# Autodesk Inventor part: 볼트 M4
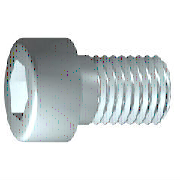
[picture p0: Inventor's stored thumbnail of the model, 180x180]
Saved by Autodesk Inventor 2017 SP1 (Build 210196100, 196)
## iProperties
IsCustomPart: 1
Created: 2012-02
Part Number: 볼트 M4
Material: 강철, 연강
Description: 6각머리 태핑 나사
Document SubType Name: Modeling
Standard: KS B 1003
Designer: mduedu
Standards Organization: KS
Language: ko-KR
Size Designation: M 4 x 10
Categories: <MemberInstance><Categories><Category DisplayName="조임쇠" InternalName="e4da775c-781d-43d5-af7c-5136215cf5a6" Mnemonic="FSTN"><Category DisplayName="볼트" InternalN
Density: 7.86 g/cm^3
Mass: 2.0371 g
Surface Area: 3.0572 cm^2
Volume: 0.259174 cm^3
Appearance: 강철
Author: mduedu
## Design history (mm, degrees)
sketch "스케치1"
  geometry: L1 (-1, 0)-(10, 0); L2 (10, 0)-(10, 2); L3 (10, 2)-(1.75, 2); L4 (1.75, 2)-(1.32, 2); L5 (1.32, 2)-(0, 2); L6 (0, 2)-(0, 3.5); L7 (0, 3.5)-(-4, 3.5); L8 (-4, 3.5)-(-4, 1.732); L9 (-4, 1.732)-(-2, 1.732); L10 (-2, 1.732)-(-1, 0); L11 (-6.8, 0)-(12.8, 0) reference; L12 (0, -0.7)-(0, 4.2) reference; L13 (1.75, 2)-(0, 2)
  constraints: 22 end point, 6 parallel, 2 collinear, 2 perpendicular, 1 horizontal, 1 point on line
  dimensions: "d1" = 8.25 distance from line of L3.end L2 (= GEL); "d2" = 0.42952 distance of L4.end L3.end (computed from GAL); "d3" = 4 distance between parallel lines of L8 L6 (= KOH); "d4" = 2 distance of L8.end L9.end (= INTI); "d5" = 60 deg angle of L10 L1; "d6" = 4 diameter of L3 L1 (= GD); "d7" = 4 diameter of L5 L1 (= BDM); "d8" = 3.4641 diameter of L9 L1 (= 1.1547 x SW); "d9" = 7 diameter of L7 L1 (= KOD); "d26" = 10 distance between parallel lines of L12 L2 (= NLG)
revolve "본체" sketch "스케치1" stored, may be unused: angle "d10" = 90 deg
sketch "스케치2"
  geometry: L1 (0, -4.9)-(0, 4.9) reference; L2 (-4.9, 0)-(4.9, 0) reference; L3 (1.732, 0)-(0.866, -1.5); L4 (0.866, -1.5)-(-0.866, -1.5); L5 (-0.866, -1.5)-(-1.732, 0); L6 (-1.732, 0)-(-0.866, 1.5); L7 (-0.866, 1.5)-(0.866, 1.5); L8 (0.866, 1.5)-(1.732, 0); 2 further points
  constraints: 12 end point, 1 coincident, 1 horizontal alignment, 1 point on line, 12 other
extrude "슬롯" join sketch "스케치2" stored distance "d11" = 10; taper "d12" = 0 deg
workplane "Work Plane1"
fillet "Fillet2" dims "d30" = 0.1 (= R)
body "Solid1"
fillet "모깎기1" dims "d17" = 0.4 (= RR)
feature "스레드" dims "d13" = 8.25 (= GEL), "d14" = 0
chamfer "모따기1" distance "d15" = 0.42941 (= -0.5 x SPD + 0.5 x GD); stored, may be unused: second distance "d16" = 0.42941 (= GUL), angle "d27" = 45 deg
other parameters: "GD" = 4 (= NND) [user parameter; used in 2 equation terms], "NLG" = 10 [user parameter; used in 1 equation term], "GEL" = 8.25 [user parameter; used in 2 equation terms], "KOD" = 7 [user parameter; used in 1 equation term], "KOH" = 4 [user parameter; used in 1 equation term], "INTI" = 2 [user parameter; used in 1 equation term], "GAL" = 0.42941 (= 0.61345 x PTC) [user parameter; used in 1 equation term], "GUL" = 0.42941 (= 0.61345 x PTC) [user parameter; used in 1 equation term], "BDM" = 4 (= NND) [user parameter; used in 1 equation term], "SW" = 3 [user parameter; used in 2 equation terms], "RR" = 0.4 [user parameter; used in 1 equation term], "SPD" = 3.14117 (= NND - 1.2269 x PTC) [user parameter; used in 1 equation term], "d19" = 0, "d28" = 0, "d29" = 0, "R" = 0.1 [user parameter; used in 1 equation term], "PHH" = 0.2 [user parameter], "GD1" = 3.14117 (= THREADDIA - 1.2269 x PTC) [user parameter], "THREADDIA" = 4 [user parameter; used in 1 equation term], "FAWI" = 45 deg [user parameter], "TPU" = 14.28571 (computed from PTC) [user parameter], "PTC" = 0.7 [user parameter; used in 5 equation terms], "NND" = 4 [user parameter; used in 3 equation terms], "TOA" = 30 deg [user parameter], "E0" = 3.465 (= 1.155 x SW) [user parameter]
